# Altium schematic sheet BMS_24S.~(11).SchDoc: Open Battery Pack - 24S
size A4; Author: Morgane Vallée; Revision: 1.0; SheetNumber: 3; SheetTotal: 5
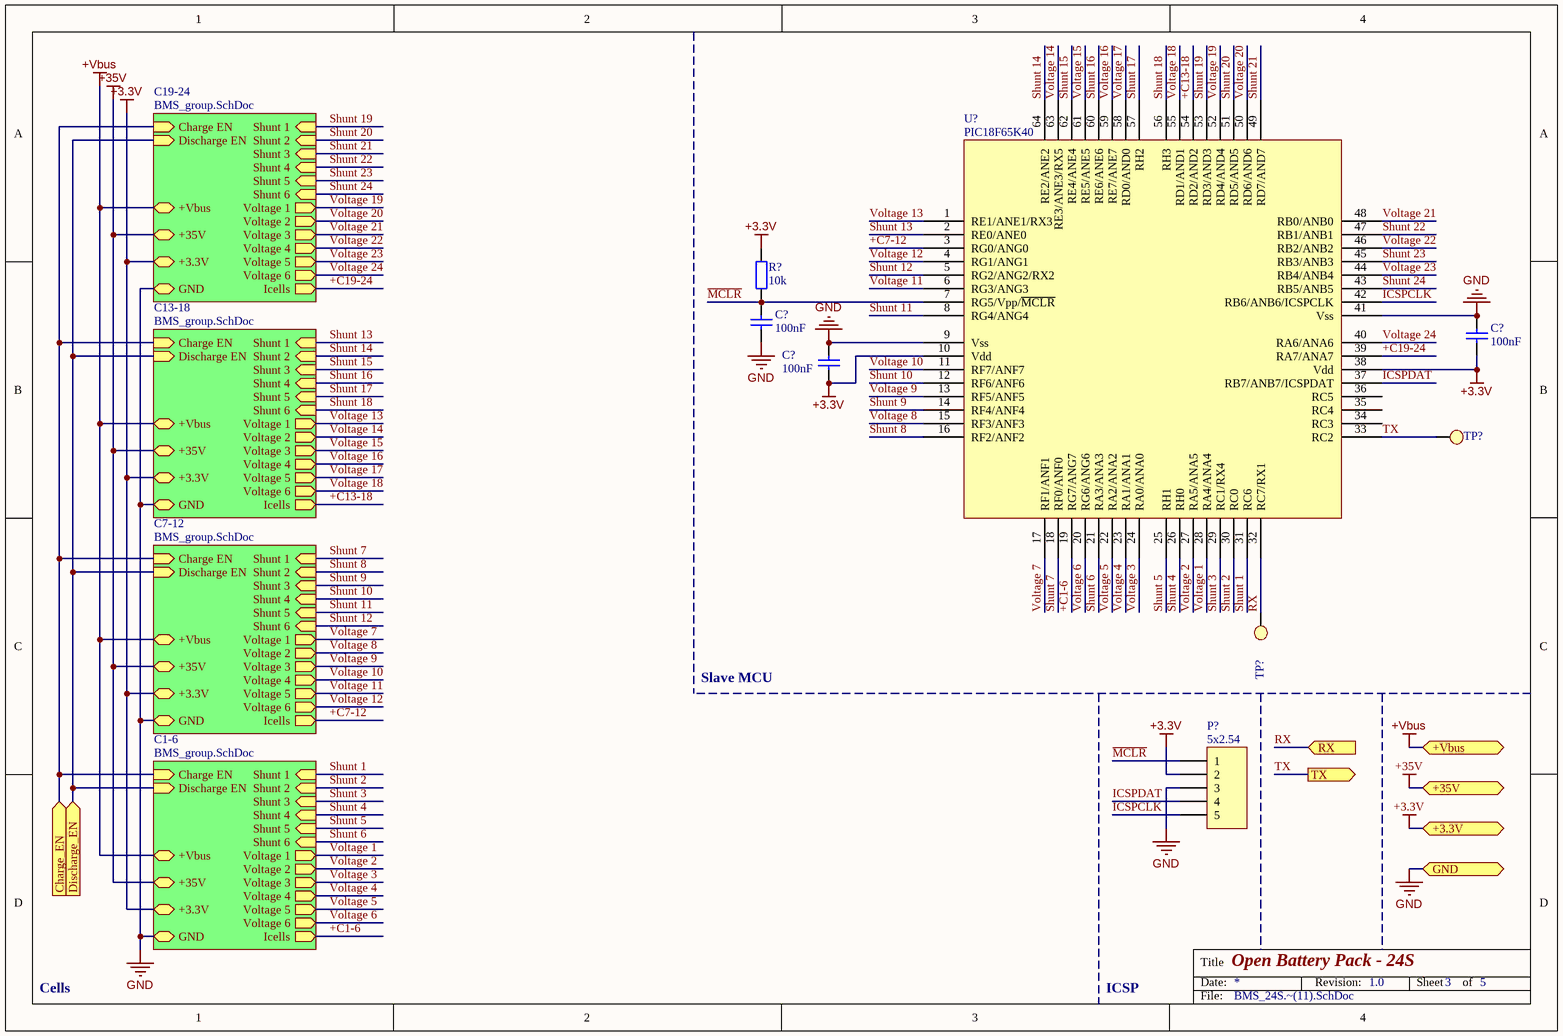
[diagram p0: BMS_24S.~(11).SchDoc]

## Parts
(Parts that share a designator on the sheet are numbered #1, #2 ... from top to bottom, then left to right.)
C?#1  100nF  [C0603]
C?#2  100nF  [C0603]
C?#3  100nF  [C0603]
P?  5x2.54  [HDR1X5]
R?  10k  [R0603]
TP?#1  Test Point  [Test Point]  (value not drawn)
TP?#2  Test Point  [Test Point]  (value not drawn)
U?  PIC18F65K40  [LQFP64]

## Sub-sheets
C1-6 = BMS_group.SchDoc: +Vbus, Shunt 1 (in), Shunt 2 (in), Shunt 3 (in), Shunt 4 (in), Shunt 5 (in), Shunt 6 (in), Voltage 1 (out), Voltage 2 (out), Voltage 3 (out), Voltage 4 (out), +3.3V, Voltage 5 (out), Voltage 6 (out), Charge EN (in), Discharge EN (in), Icells (out), GND, +35V
C7-12 = BMS_group.SchDoc: +Vbus, Shunt 1 (in), Shunt 2 (in), Shunt 3 (in), Shunt 4 (in), Shunt 5 (in), Shunt 6 (in), Voltage 1 (out), Voltage 2 (out), Voltage 3 (out), Voltage 4 (out), +3.3V, Voltage 5 (out), Voltage 6 (out), Charge EN (in), Discharge EN (in), Icells (out), GND, +35V
C13-18 = BMS_group.SchDoc: +Vbus, Shunt 1 (in), Shunt 2 (in), Shunt 3 (in), Shunt 4 (in), Shunt 5 (in), Shunt 6 (in), Voltage 1 (out), Voltage 2 (out), Voltage 3 (out), Voltage 4 (out), +3.3V, Voltage 5 (out), Voltage 6 (out), Charge EN (in), Discharge EN (in), Icells (out), GND, +35V
C19-24 = BMS_group.SchDoc: +Vbus, Shunt 1 (in), Shunt 2 (in), Shunt 3 (in), Shunt 4 (in), Shunt 5 (in), Shunt 6 (in), Voltage 1 (out), Voltage 2 (out), Voltage 3 (out), Voltage 4 (out), +3.3V, Voltage 5 (out), Voltage 6 (out), Charge EN (in), Discharge EN (in), Icells (out), GND, +35V

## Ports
+3.3V, +35V, +Vbus, Charge_EN (in), Discharge_EN (in), GND, RX (in), TX (out)

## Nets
+3.3V: C?#2.2 C?#3.2 P?.2 R?.2 U?.10(Vdd) U?.38(Vdd) ; port +3.3V, sheet C1-6/+3.3V, sheet C7-12/+3.3V, sheet C13-18/+3.3V, sheet C19-24/+3.3V
+35V: port +35V, sheet C1-6/+35V, sheet C7-12/+35V, sheet C13-18/+35V, sheet C19-24/+35V
+Vbus: port +Vbus, sheet C1-6/+Vbus, sheet C7-12/+Vbus, sheet C13-18/+Vbus, sheet C19-24/+Vbus
GND: C?#1.1 C?#2.1 C?#3.1 P?.3 U?.9(Vss) U?.41(Vss) ; port GND, sheet C1-6/GND, sheet C7-12/GND, sheet C13-18/GND, sheet C19-24/GND
+C1-6: U?.19(RG7/ANG7) ; sheet C1-6/Icells
+C7-12: U?.3(RG0/ANG0) ; sheet C7-12/Icells
+C13-18: U?.54(RD2/AND2) ; sheet C13-18/Icells
+C19-24: U?.39(RA7/ANA7) ; sheet C19-24/Icells
Charge_EN: port Charge_EN, sheet C1-6/Charge EN, sheet C7-12/Charge EN, sheet C13-18/Charge EN, sheet C19-24/Charge EN
Discharge_EN: port Discharge_EN, sheet C1-6/Discharge EN, sheet C7-12/Discharge EN, sheet C13-18/Discharge EN, sheet C19-24/Discharge EN
ICSPCLK: P?.5 U?.42(RB6/ANB6/ICSPCLK)
ICSPDAT: P?.4 U?.37(RB7/ANB7/ICSPDAT)
~{MCLR}: C?#1.2 P?.1 R?.1 U?.7(RG5/Vpp/~{MCLR})
RX: TP?#2.1 U?.32(RC7/RX1) ; port RX
Shunt 1: U?.31(RC6) ; sheet C1-6/Shunt 1
Shunt 2: U?.30(RC0) ; sheet C1-6/Shunt 2
Shunt 3: U?.29(RC1/RX4) ; sheet C1-6/Shunt 3
Shunt 4: U?.26(RH0) ; sheet C1-6/Shunt 4
Shunt 5: U?.25(RH1) ; sheet C1-6/Shunt 5
Shunt 6: U?.21(RA3/ANA3) ; sheet C1-6/Shunt 6
Shunt 7: U?.18(RF0/ANF0) ; sheet C7-12/Shunt 1
Shunt 8: U?.16(RF2/ANF2) ; sheet C7-12/Shunt 2
Shunt 9: U?.14(RF4/ANF4) ; sheet C7-12/Shunt 3
Shunt 10: U?.12(RF6/ANF6) ; sheet C7-12/Shunt 4
Shunt 11: U?.8(RG4/ANG4) ; sheet C7-12/Shunt 5
Shunt 12: U?.5(RG2/ANG2/RX2) ; sheet C7-12/Shunt 6
Shunt 13: U?.2(RE0/ANE0) ; sheet C13-18/Shunt 1
Shunt 14: U?.64(RE2/ANE2) ; sheet C13-18/Shunt 2
Shunt 15: U?.62(RE4/ANE4) ; sheet C13-18/Shunt 3
Shunt 16: U?.60(RE6/ANE6) ; sheet C13-18/Shunt 4
Shunt 17: U?.57(RH2) ; sheet C13-18/Shunt 5
Shunt 18: U?.56(RH3) ; sheet C13-18/Shunt 6
Shunt 19: U?.53(RD3/AND3) ; sheet C19-24/Shunt 1
Shunt 20: U?.51(RD5/AND5) ; sheet C19-24/Shunt 2
Shunt 21: U?.49(RD7/AND7) ; sheet C19-24/Shunt 3
Shunt 22: U?.47(RB1/ANB1) ; sheet C19-24/Shunt 4
Shunt 23: U?.45(RB3/ANB3) ; sheet C19-24/Shunt 5
Shunt 24: U?.43(RB5/ANB5) ; sheet C19-24/Shunt 6
TX: TP?#1.1 U?.33(RC2) ; port TX
Voltage 1: U?.28(RA4/ANA4) ; sheet C1-6/Voltage 1
Voltage 2: U?.27(RA5/ANA5) ; sheet C1-6/Voltage 2
Voltage 3: U?.24(RA0/ANA0) ; sheet C1-6/Voltage 3
Voltage 4: U?.23(RA1/ANA1) ; sheet C1-6/Voltage 4
Voltage 5: U?.22(RA2/ANA2) ; sheet C1-6/Voltage 5
Voltage 6: U?.20(RG6/ANG6) ; sheet C1-6/Voltage 6
Voltage 7: U?.17(RF1/ANF1) ; sheet C7-12/Voltage 1
Voltage 8: U?.15(RF3/ANF3) ; sheet C7-12/Voltage 2
Voltage 9: U?.13(RF5/ANF5) ; sheet C7-12/Voltage 3
Voltage 10: U?.11(RF7/ANF7) ; sheet C7-12/Voltage 4
Voltage 11: U?.6(RG3/ANG3) ; sheet C7-12/Voltage 5
Voltage 12: U?.4(RG1/ANG1) ; sheet C7-12/Voltage 6
Voltage 13: U?.1(RE1/ANE1/RX3) ; sheet C13-18/Voltage 1
Voltage 14: U?.63(RE3/ANE3/RX5) ; sheet C13-18/Voltage 2
Voltage 15: U?.61(RE5/ANE5) ; sheet C13-18/Voltage 3
Voltage 16: U?.59(RE7/ANE7) ; sheet C13-18/Voltage 4
Voltage 17: U?.58(RD0/AND0) ; sheet C13-18/Voltage 5
Voltage 18: U?.55(RD1/AND1) ; sheet C13-18/Voltage 6
Voltage 19: U?.52(RD4/AND4) ; sheet C19-24/Voltage 1
Voltage 20: U?.50(RD6/AND6) ; sheet C19-24/Voltage 2
Voltage 21: U?.48(RB0/ANB0) ; sheet C19-24/Voltage 3
Voltage 22: U?.46(RB2/ANB2) ; sheet C19-24/Voltage 4
Voltage 23: U?.44(RB4/ANB4) ; sheet C19-24/Voltage 5
Voltage 24: U?.40(RA6/ANA6) ; sheet C19-24/Voltage 6

Not connected (* = marked no-connect by the designer): U? 34(RC3) 35(RC4) 36(RC5)

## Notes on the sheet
- Slave MCU
- Cells
- ICSP

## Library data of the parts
C?#1-C?#3 = Cap: Capacitor
P? = Header 5: Header, 5-Pin
R? = Res2: Resistor
U? = PIC18F65K40: 64-Pin, Low-Power, High-Performance Microcontrollers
